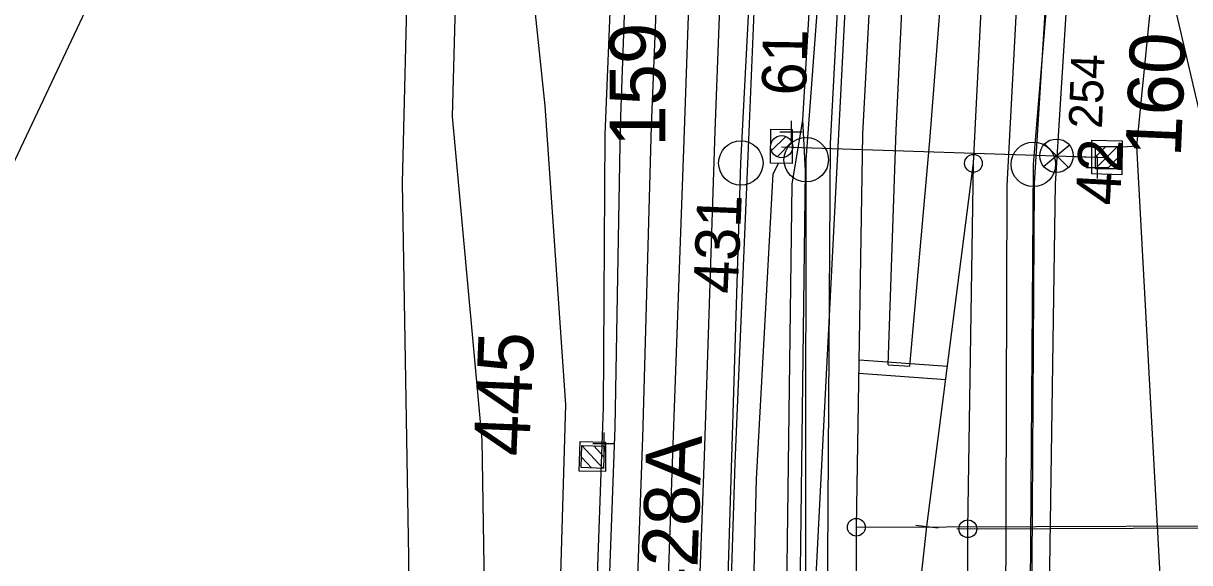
# Model space of a CAD drawing. Extents: x -598638 to -597933, y -1164002 to -1161904.
# Drawn here: x -598282.7 to -598230.2, y -1163148.3 to -1163124 of the extents above; entities that cross this region are included whole.
import ezdxf

# ---------------------------------------------------------------- set-up
doc = ezdxf.new("R2010")
doc.units = 0
for name, color, linetype in [('Vrstva 1', 7, 'Continuous'), ('Vrstva 11', 7, 'Continuous'), ('Vrstva 12', 7, 'Continuous'), ('Vrstva 2', 7, 'Continuous'), ('Vrstva 25', 7, 'Continuous'), ('Vrstva 26', 7, 'Continuous'), ('Vrstva 28', 7, 'Continuous'), ('Vrstva 4', 7, 'Continuous'), ('Vrstva 43', 7, 'Continuous'), ('Vrstva 44', 7, 'Continuous'), ('Vrstva 49', 7, 'Continuous'), ('Vrstva 51', 7, 'Continuous'), ('Vrstva 63', 7, 'Continuous'), ('Vrstva 7', 7, 'Continuous')]:
    doc.layers.add(name, color=color, linetype=linetype)

msp = doc.modelspace()

# ---------------------------------------------------------------- linework, layer by layer
at = {"layer": 'Vrstva 1'}
for p, q in [((-598242.008, -1163146.652), (-598239.921, -1163130.309)), ((-598245.185, -1163146.686), (-598168.351, -1163146.421)), ((-598245.146, -1163158.452), (-598245.185, -1163146.686)), ((-598240.169, -1163146.755), (-598170.081, -1163146.513))]:
    msp.add_line(p, q, dxfattribs=at)
for points in [[(-598245.185, -1163146.686), (-598244.89, -1163128.996), (-598244.069, -1163113.383), (-598243.892, -1163111.402), (-598242.508, -1163095.903), (-598240.221, -1163078.173), (-598237.7, -1163063), (-598234.456, -1163047.036), (-598230.819, -1163031.867), (-598224.044, -1163008.196), (-598218.147, -1162990.962), (-598212.612, -1162976.381), (-598210.162, -1162970.38), (-598207.127, -1162963.269), (-598201.66, -1162951.286), (-598200.923, -1162949.67), (-598193.375, -1162934.568), (-598185.535, -1162920.228)], [(-598240.169, -1163146.755), (-598239.921, -1163130.309), (-598239.07, -1163113.566), (-598238.926, -1163111.785), (-598238.259, -1163103.539), (-598237.54, -1163096.536), (-598235.247, -1163078.679), (-598233.075, -1163065.413), (-598229.628, -1163048.216), (-598226.08, -1163033.339), (-598219.335, -1163009.739), (-598213.514, -1162992.625), (-598208.094, -1162978.373), (-598205.572, -1162972.188), (-598202.745, -1162965.549), (-598196.38, -1162951.607), (-598188.854, -1162936.558), (-598181.238, -1162922.581)], [(-598254.941, -1163186.204), (-598253.423, -1163142.963), (-598252.923, -1163128.846), (-598252.219, -1163108.544)], [(-598243.311, -1163158.553), (-598242.682, -1163152.788), (-598242.008, -1163146.652)], [(-598239.731, -1163287.87), (-598239.846, -1163247.571), (-598239.957, -1163214.082), (-598239.963, -1163212.175), (-598240, -1163201.726), (-598240.089, -1163175.503), (-598240.169, -1163146.755)]]:
    msp.add_lwpolyline(points, dxfattribs=at)
for centre in [(-598245.185, -1163146.686), (-598240.169, -1163146.755)]:
    msp.add_circle(centre, 0.4, dxfattribs=at)
at = {"layer": 'Vrstva 11'}
for p, q in [((-598249.011, -1163129.744), (-598248.365, -1163129.098)), ((-598248.751, -1163130.014), (-598248.096, -1163129.359)), ((-598234.43, -1163130.017), (-598233.963, -1163129.55)), ((-598234.43, -1163130.547), (-598233.433, -1163129.55)), ((-598233.903, -1163130.55), (-598233.43, -1163130.077)), ((-598256.572, -1163144.038), (-598257.531, -1163143.005)), ((-598256.549, -1163143.512), (-598257.004, -1163143.021)), ((-598257.102, -1163144.018), (-598257.551, -1163143.534))]:
    msp.add_line(p, q, dxfattribs=at)
for points in [[(-598248.55, -1163129.56), (-598233.93, -1163130.05)], [(-598234.43, -1163129.55), (-598233.43, -1163129.55), (-598233.43, -1163130.55), (-598234.43, -1163130.55), (-598234.43, -1163129.55)], [(-598257.568, -1163144.001), (-598257.531, -1163143.002), (-598256.532, -1163143.039), (-598256.569, -1163144.038), (-598257.568, -1163144.001)]]:
    msp.add_lwpolyline(points, dxfattribs=at)
for points in [[(-598234.43, -1163129.55), (-598233.43, -1163129.55), (-598233.43, -1163130.55), (-598234.43, -1163130.55)], [(-598257.568, -1163144.001), (-598257.531, -1163143.002), (-598256.532, -1163143.039), (-598256.569, -1163144.038)]]:
    msp.add_lwpolyline(points, close=True, dxfattribs=at)
msp.add_circle((-598248.55, -1163129.56), 0.5, dxfattribs=at)
at = {"layer": 'Vrstva 12'}
for points in [[(-598248.07, -1163128.78), (-598248.08, -1163130.31), (-598249.05, -1163130.3), (-598249.04, -1163128.77), (-598248.07, -1163128.78)], [(-598234.59, -1163130.78), (-598234.59, -1163129.27), (-598233.23, -1163129.3), (-598233.24, -1163130.82), (-598234.59, -1163130.78)], [(-598256.47, -1163142.86), (-598256.48, -1163144.18), (-598257.66, -1163144.16), (-598257.61, -1163142.83), (-598256.47, -1163142.86)]]:
    msp.add_lwpolyline(points, dxfattribs=at)
at = {"layer": 'Vrstva 2'}
for p, q in [((-598242.505, -1163146.597), (-598241.511, -1163146.707)), ((-598240.669, -1163146.747), (-598239.669, -1163146.763))]:
    msp.add_line(p, q, dxfattribs=at)
for points in [[(-598240.169, -1163146.755), (-598239.921, -1163130.309), (-598239.07, -1163113.566)], [(-598242.008, -1163146.652), (-598239.921, -1163130.309)]]:
    msp.add_lwpolyline(points, dxfattribs=at)
msp.add_circle((-598239.917, -1163130.31), 0.4, dxfattribs=at)
at = {"layer": 'Vrstva 25'}
for p, q in [((-598236.765, -1163130.446), (-598235.604, -1163129.484)), ((-598236.713, -1163129.432), (-598235.642, -1163130.494)), ((-598235.429, -1163129.997), (-598233.93, -1163130.05))]:
    msp.add_line(p, q, dxfattribs=at)
msp.add_circle((-598236.179, -1163129.968), 0.754, dxfattribs=at)
at = {"layer": 'Vrstva 26'}
for points in [[(-598211.382, -1162940.065), (-598193.601, -1162950.161), (-598191.584, -1162951.092), (-598198.026, -1162967.205), (-598208.688, -1162993.504), (-598209.03, -1162994.474), (-598214.707, -1163009.33), (-598218.558, -1163024.082), (-598220.34, -1163031.684), (-598220.756, -1163034.417), (-598224.218, -1163049.876), (-598227.646, -1163065.71), (-598228.067, -1163068.213), (-598230.531, -1163097), (-598231.676, -1163107.807), (-598231.723, -1163120.907), (-598232.574, -1163129.537), (-598231.426, -1163150.759)], [(-598232.574, -1163129.537), (-598233.209, -1163129.579), (-598233.511, -1163129.582)]]:
    msp.add_lwpolyline(points, dxfattribs=at)
at = {"layer": 'Vrstva 28'}
msp.add_lwpolyline([(-598311.69, -1163165.97), (-598300.22, -1163144.81), (-598288.63, -1163123.27), (-598282.38, -1163112.74), (-598276.94, -1163103.58), (-598276.43, -1163102.81), (-598275.67, -1163101.85), (-598275.32, -1163101.07), (-598273.79, -1163098.83), (-598261.6, -1163097.17), (-598260.92, -1163098.05), (-598264.78, -1163103.58), (-598264.9, -1163104.07), (-598265.13, -1163109.86), (-598265.13, -1163112.72), (-598265.03, -1163116.78), (-598265.37, -1163120.79), (-598265.62, -1163131.18), (-598265.34, -1163148.04), (-598265.46, -1163176.63)], dxfattribs=at)
at = {"layer": 'Vrstva 4'}
for points in [[(-598398.167, -1163553.239), (-598376.487, -1163515.918), (-598348.795, -1163467.979), (-598339.716, -1163452.202), (-598323.266, -1163423.236), (-598308.372, -1163396.471), (-598302.715, -1163384.123), (-598298.324, -1163372.137), (-598289.593, -1163344.221), (-598282.967, -1163321.229), (-598274.797, -1163290.285), (-598269.404, -1163272.781), (-598266.519, -1163258.633), (-598263.896, -1163241.651), (-598261.185, -1163218.05), (-598260.503, -1163217.001), (-598259.092, -1163201.513), (-598258.163, -1163186.176), (-598256.557, -1163141.317), (-598256.485, -1163129.008), (-598255.651, -1163108.451), (-598254.34, -1163087.718), (-598253.319, -1163075.132)], [(-598321.684, -1163563.952), (-598314.649, -1163552.341), (-598302.065, -1163529.781), (-598292.77, -1163512.02), (-598281.731, -1163489.572), (-598274.163, -1163472.668), (-598266.066, -1163452.17), (-598258.953, -1163431.709), (-598252.674, -1163410.241), (-598246.46, -1163386.104), (-598243.144, -1163368.884), (-598239.955, -1163345.756), (-598237.56, -1163323.253), (-598236.679, -1163305.47), (-598236.283, -1163282.744), (-598236.431, -1163244.569), (-598236.596, -1163214.625), (-598236.873, -1163174.881), (-598236.229, -1163131.239), (-598234.781, -1163108.249), (-598234.285, -1163099.455), (-598231.787, -1163078.342)], [(-598283.36, -1163489.15), (-598275.736, -1163471.917), (-598267.551, -1163451.028), (-598260.793, -1163431.262), (-598254.345, -1163409.722), (-598248.47, -1163385.636), (-598245.045, -1163368.352), (-598241.712, -1163345.6), (-598239.462, -1163322.753), (-598238.478, -1163305.467), (-598238.203, -1163283.28), (-598238.406, -1163245.16), (-598238.376, -1163215.168), (-598238.53, -1163175.26), (-598238.394, -1163131.328), (-598237.202, -1163108.683), (-598236.122, -1163097.625), (-598233.737, -1163078.205)], [(-598307.376, -1163503.64), (-598306.256, -1163500.72), (-598304.527, -1163496.743), (-598299.478, -1163486.144), (-598290.117, -1163465.204), (-598280.795, -1163442.724), (-598274.814, -1163425.66), (-598269.09, -1163405.616), (-598262.907, -1163380.487), (-598260.225, -1163366.071), (-598256.638, -1163342.661), (-598254.612, -1163322.432), (-598252.977, -1163304.928), (-598251.437, -1163287.268), (-598250.068, -1163266.224), (-598248.818, -1163245.446), (-598248.467, -1163214.545), (-598248.623, -1163173.63), (-598248.072, -1163131.254), (-598247.596, -1163128.349)], [(-598388.69, -1163572.819), (-598382.701, -1163561.089), (-598361.383, -1163524.292), (-598334.6, -1163477.579), (-598308.353, -1163432.12), (-598292.471, -1163404.257), (-598285.937, -1163390.16), (-598281.631, -1163378.652), (-598277.216, -1163365.008), (-598272.579, -1163348.284), (-598269.387, -1163336.75), (-598267.113, -1163324.869), (-598262.674, -1163291.919), (-598258.642, -1163259.137), (-598254.182, -1163220.99), (-598251.647, -1163201.068), (-598250.766, -1163187.503), (-598249.671, -1163144.519), (-598248.922, -1163130.776), (-598248.69, -1163130.313)]]:
    msp.add_lwpolyline(points, dxfattribs=at)
at = {"layer": 'Vrstva 43'}
for centre in [(-598250.383, -1163130.296), (-598247.442, -1163130.148), (-598237.218, -1163130.355)]:
    msp.add_circle(centre, 1, dxfattribs=at)
at = {"layer": 'Vrstva 44'}
for points in [[(-598295.758, -1163493.483), (-598278.118, -1163452.874), (-598264.209, -1163410.565), (-598254.468, -1163367.19), (-598248.62, -1163321.577), (-598253.497, -1163320.887), (-598249.615, -1163272.581), (-598247.635, -1163222.481), (-598247.486, -1163176.779), (-598247.442, -1163130.148), (-598244.014, -1163084.171), (-598235.33, -1163037.762), (-598224.817, -1163002.559), (-598219.379, -1163002.169), (-598206.652, -1162968.487), (-598191.401, -1162936.053), (-598173.754, -1162904.506), (-598155.689, -1162873.083), (-598136.14, -1162838.446), (-598116.776, -1162804.197)], [(-598286.823, -1163498.793), (-598268.977, -1163457.491), (-598254.684, -1163414.899), (-598244.494, -1163370.7), (-598238.629, -1163323.594), (-598237.183, -1163277.386), (-598237.387, -1163227.403), (-598237.546, -1163176.839), (-598237.218, -1163130.355), (-598233.358, -1163084.011), (-598224.142, -1163038.365), (-598215.269, -1163005.578), (-598224.817, -1163002.559)], [(-598280.199, -1163332.648), (-598271.397, -1163301.809), (-598265.446, -1163302.712), (-598259.208, -1163252.741), (-598251.788, -1163176.385), (-598250.383, -1163130.296), (-598247.948, -1163083.491), (-598241.007, -1163044.927)]]:
    msp.add_lwpolyline(points, dxfattribs=at)
at = {"layer": 'Vrstva 49'}
for points in [[(-598299.445, -1163361.058), (-598297.068, -1163359.059), (-598293.068, -1163343.621), (-598287.79, -1163320.649), (-598279.637, -1163288.312), (-598274.636, -1163271.434), (-598271.523, -1163257.595), (-598269.283, -1163241.904), (-598267.104, -1163218.072), (-598264.127, -1163206.783), (-598263.144, -1163204.971), (-598260.62, -1163202.843), (-598259.578, -1163186.018), (-598258.253, -1163141.176), (-598259.192, -1163127.718), (-598260.075, -1163119.279), (-598261.182, -1163115.692), (-598261.349, -1163113.122), (-598258.894, -1163101.538), (-598255.65, -1163087.809), (-598254.518, -1163075.132), (-598252.098, -1163061.479), (-598247.841, -1163044.835)], [(-598218.985, -1163327.148), (-598212.65, -1163283.715), (-598208.558, -1163248.195), (-598210.74, -1163214.935), (-598218.187, -1163174.338), (-598225.543, -1163145.969), (-598230.824, -1163123.355), (-598234.781, -1163108.249)], [(-598271.914, -1163217.222), (-598269.776, -1163209.288), (-598269.073, -1163206.337), (-598265.809, -1163203.939), (-598262.679, -1163201.583), (-598261.749, -1163188.913), (-598261.649, -1163166.383), (-598262.017, -1163142.76), (-598263.36, -1163128.202), (-598263.105, -1163118.751), (-598268.545, -1163115.616), (-598275.334, -1163113.816), (-598312.096, -1163191.704), (-598312.746, -1163196.691)]]:
    msp.add_lwpolyline(points, dxfattribs=at)
at = {"layer": 'Vrstva 51'}
for points in [[(-598243.76, -1163139.382), (-598243.393, -1163128.836), (-598242.662, -1163113.52), (-598241.121, -1163096.732), (-598238.542, -1163077.297), (-598236.364, -1163063.881), (-598233.006, -1163047.35), (-598229.452, -1163032.186), (-598222.566, -1163008.635), (-598216.788, -1162991.447), (-598211.314, -1162977.141), (-598198.954, -1162949.031), (-598191.954, -1162935.136), (-598181.215, -1162915.654), (-598172.367, -1162900.092), (-598146.639, -1162854.694), (-598125.435, -1162817.431), (-598123.403, -1162813.873), (-598093.874, -1162762.323), (-598071.494, -1162722.83), (-598058.726, -1162701.732), (-598043.403, -1162678.606), (-598026.165, -1162652.845)], [(-598397.431, -1163553.318), (-598375.745, -1163515.943), (-598348.098, -1163468.333), (-598322.38, -1163423.533), (-598307.542, -1163396.818), (-598301.86, -1163384.541), (-598297.285, -1163372.341), (-598293.283, -1163359.379), (-598288.845, -1163344.448), (-598282.25, -1163321.235), (-598273.825, -1163290.423), (-598265.756, -1163258.778), (-598260.545, -1163219.203), (-598259.744, -1163217.171), (-598258.57, -1163201.891), (-598257.659, -1163186.255), (-598256.038, -1163142.193), (-598255.793, -1163128.623), (-598255.065, -1163108.27), (-598253.781, -1163088.998), (-598252.62, -1163075.466)], [(-598396.078, -1163554.151), (-598374.443, -1163516.599), (-598347.031, -1163469.014), (-598321.218, -1163424.261), (-598306.253, -1163397.723), (-598300.608, -1163385.153), (-598295.814, -1163372.93), (-598291.849, -1163359.988), (-598287.46, -1163344.41), (-598281.154, -1163322.32), (-598272.412, -1163291.197), (-598264.229, -1163259.135), (-598258.972, -1163219.27), (-598257.327, -1163201.644), (-598256.369, -1163186.491), (-598254.79, -1163142.649), (-598254.397, -1163128.629), (-598253.571, -1163108.317), (-598252.585, -1163090.153), (-598250.983, -1163076.012)], [(-598384.985, -1163560.822), (-598363.176, -1163523.063), (-598335.955, -1163475.581), (-598310.179, -1163431.066), (-598295.149, -1163404.135), (-598288.465, -1163389.583), (-598283.96, -1163377.815), (-598279.772, -1163364.473), (-598275.196, -1163348.33), (-598271.933, -1163336.198), (-598269.31, -1163324.265), (-598265.084, -1163292.029), (-598261.053, -1163259.678), (-598256.104, -1163220.296), (-598254.426, -1163201.671), (-598253.667, -1163187.936), (-598252.018, -1163143.494), (-598251.534, -1163128.863), (-598250.791, -1163108.998), (-598250.069, -1163094.383), (-598248.218, -1163076.729)], [(-598305.922, -1163504.285), (-598297.335, -1163487.137), (-598287.92, -1163465.981), (-598279.035, -1163443.103), (-598273.208, -1163425.978), (-598267.2, -1163406.108), (-598261.011, -1163380.887), (-598258.166, -1163366.304), (-598254.569, -1163343.143), (-598252.435, -1163322.084), (-598250.965, -1163305.051), (-598249.488, -1163286.133), (-598247.962, -1163266.793), (-598246.718, -1163245.404), (-598246.637, -1163214.417), (-598246.633, -1163173.748), (-598246.347, -1163129.422), (-598245.484, -1163112.939), (-598244.076, -1163096.672), (-598241.475, -1163076.865)], [(-598298.888, -1163486.593), (-598289.113, -1163465.583), (-598279.905, -1163442.964), (-598274.107, -1163425.699), (-598268.268, -1163405.757), (-598262.238, -1163380.596), (-598259.701, -1163366.461), (-598255.999, -1163342.847), (-598253.859, -1163322.319), (-598252.407, -1163304.609), (-598250.982, -1163286.31), (-598249.458, -1163266.6), (-598248.128, -1163245.447), (-598247.963, -1163214.31), (-598248.01, -1163173.778), (-598247.475, -1163130.652), (-598247.596, -1163128.349), (-598246.685, -1163112.866), (-598245.177, -1163096.514), (-598242.921, -1163076.624)], [(-598389.422, -1163572.47), (-598383.242, -1163561.018), (-598361.933, -1163523.985), (-598335.337, -1163477.363), (-598309.065, -1163431.797), (-598293.626, -1163404.644), (-598286.924, -1163390.082), (-598282.523, -1163378.361), (-598278.252, -1163364.663), (-598273.758, -1163348.557), (-598270.372, -1163336.656), (-598267.892, -1163324.623), (-598263.657, -1163291.858), (-598259.724, -1163259.57), (-598255.007, -1163220.516), (-598252.865, -1163201.196), (-598252.034, -1163187.935), (-598250.643, -1163143.798), (-598250.023, -1163129.244), (-598249.184, -1163109.078), (-598248.423, -1163094.475), (-598246.693, -1163077.089)], [(-598243.76, -1163139.382), (-598242.782, -1163139.432), (-598241.873, -1163129.303), (-598240.653, -1163113.474), (-598239.095, -1163097.092), (-598236.576, -1163077.501)], [(-598282.309, -1163489.477), (-598274.667, -1163472.413), (-598266.77, -1163451.853), (-598259.621, -1163431.675), (-598253.513, -1163410.04), (-598247.112, -1163385.98), (-598243.846, -1163368.944), (-598240.561, -1163345.639), (-598238.081, -1163322.667), (-598237.343, -1163305.453), (-598236.795, -1163282.909), (-598237.051, -1163244.829), (-598237.298, -1163214.833), (-598237.439, -1163175.203), (-598237.167, -1163131.222), (-598235.767, -1163108.629), (-598234.985, -1163097.818), (-598232.528, -1163078.41)]]:
    msp.add_lwpolyline(points, dxfattribs=at)
at = {"layer": 'Vrstva 63'}
msp.add_line((-598248.331, -1163175.227), (-598242.563, -1163062.027), dxfattribs=at)
at = {"layer": 'Vrstva 7'}
for p, q in [((-598248.121, -1163128.394), (-598248.121, -1163129.394)), ((-598248.621, -1163128.894), (-598247.621, -1163128.894)), ((-598234.352, -1163129.999), (-598234.352, -1163130.999)), ((-598234.852, -1163130.499), (-598233.852, -1163130.499)), ((-598245.059, -1163139.152), (-598241.087, -1163139.438)), ((-598245.069, -1163139.753), (-598241.163, -1163140.034)), ((-598256.546, -1163142.423), (-598256.546, -1163143.423)), ((-598257.046, -1163142.923), (-598256.046, -1163142.923))]:
    msp.add_line(p, q, dxfattribs=at)

# ---------------------------------------------------------------- texts
at = {"layer": 'Vrstva 1'}
msp.add_text('428A', height=2.5, rotation=87.9894, dxfattribs=at).set_placement((-598252.402, -1163150.377))
at = {"layer": 'Vrstva 11'}
for s, rotation, p in [('159', 90, (-598253.782, -1163129.56)), ('160', 87.5507, (-598230.589, -1163130.05)), ('445', 87.5834, (-598259.916, -1163143.52))]:
    msp.add_text(s, height=2.5, rotation=rotation, dxfattribs=at).set_placement(p)
at = {"layer": 'Vrstva 25'}
msp.add_text('254', height=1.5, rotation=87.9716, dxfattribs=at).set_placement((-598234.135, -1163128.765))
at = {"layer": 'Vrstva 43'}
for s, rotation, p in [('61', 89.0446, (-598247.442, -1163127.265)), ('42', 87.0903, (-598233.328, -1163132.229)), ('431', 87.5607, (-598250.527, -1163136.206))]:
    msp.add_text(s, height=2, rotation=rotation, dxfattribs=at).set_placement(p)

doc.saveas('drawing.dxf')
